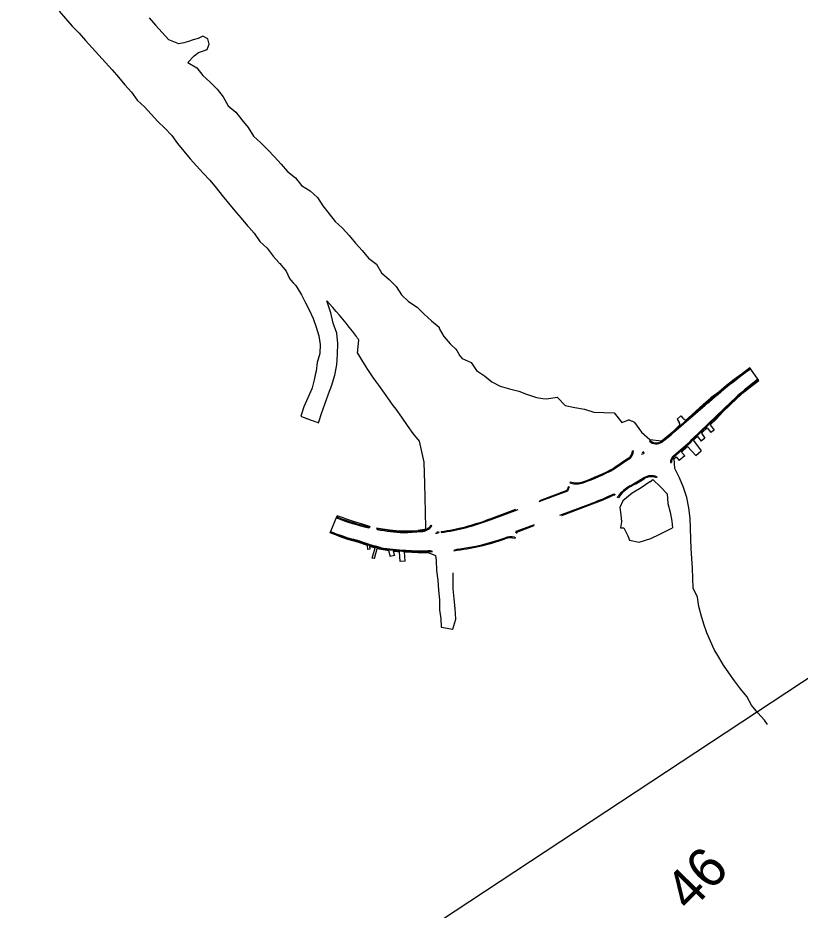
# Model space of a CAD drawing. Extents: x -5665 to 1997148, y 4 to 812485.
# Drawn here: x 1961620 to 1965586, y 802527 to 807051 of the extents above; entities that cross this region are included whole.
import ezdxf

# ---------------------------------------------------------------- set-up
doc = ezdxf.new("R2010")
doc.units = 0
for name, color, linetype in [('RD_PD_CstnLmt', 7, 'Continuous'), ('RD_PD_SW', 7, 'Continuous'), ('RD_SHT_ShtClip', 7, 'Continuous'), ('RD_SHT_TX', 7, 'Continuous')]:
    doc.layers.add(name, color=color, linetype=linetype)

msp = doc.modelspace()

# ---------------------------------------------------------------- linework, layer by layer
at = {"layer": 'RD_PD_CstnLmt'}
for p, q in [((1963199.4, 805601.5), (1963186.1, 805616.2)), ((1963342.6, 805350.3), (1963349.6, 805416.2)), ((1965095.2, 805090.2), (1965133, 805123.9)), ((1965058.2, 805056.4), (1965095.2, 805090.2)), ((1964981.6, 805033.9), (1964962.9, 805017)), ((1964962.9, 805017), (1964973.4, 804999.3)), ((1964981.6, 805033.9), (1964991.7, 805021.6)), ((1965007.8, 805012.6), (1965021.1, 805023)), ((1965021.1, 805023), (1965058.2, 805056.4)), ((1964745.4, 805000.5), (1964746.8, 804999.9)), ((1964945.4, 804957.6), (1964976.9, 804987.8)), ((1965115.5, 804972.6), (1965134, 804947.9)), ((1965130.6, 804986.9), (1965150.6, 804960.3)), ((1964908.6, 804926), (1964945.4, 804957.6)), ((1965066.6, 804928.3), (1965083.9, 804905.2)), ((1965085.6, 804945.1), (1965102.8, 804919.3)), ((1965150.6, 804960.3), (1965134, 804947.9)), ((1964883.5, 804906), (1964908.6, 804926)), ((1965045.5, 804908.8), (1965051.3, 804914.8)), ((1965045.5, 804908.8), (1965084.7, 804855.6)), ((1965102.8, 804919.3), (1965083.9, 804905.2)), ((1964984.8, 804849.7), (1965015.7, 804877.6)), ((1964984.8, 804849.7), (1965001.2, 804830.1)), ((1965015.7, 804877.6), (1965057.6, 804831.2)), ((1965057.6, 804831.2), (1965084.7, 804855.6)), ((1964948.5, 804817), (1964957.6, 804825.2)), ((1964957.6, 804825.2), (1964973.1, 804806.7)), ((1965001.2, 804830.1), (1964973.1, 804806.7)), ((1963204.3, 804440.1), (1963238.4, 804526)), ((1963274.8, 804513.8), (1963238.4, 804526)), ((1963274.8, 804513.8), (1963320.2, 804499.7)), ((1963320.2, 804499.7), (1963365.9, 804486.4)), ((1963365.9, 804486.4), (1963406.6, 804472.3)), ((1963243.2, 804425.4), (1963204.3, 804440.1)), ((1963437.9, 804465.4), (1963458, 804461.4)), ((1963458, 804461.4), (1963505.2, 804454.5)), ((1963505.2, 804454.5), (1963552.8, 804449.8)), ((1963552.8, 804449.8), (1963600.5, 804449.4)), ((1963600.5, 804449.4), (1963648.1, 804452.4)), ((1963682.7, 804456.3), (1963648.1, 804452.4)), ((1963243.2, 804425.4), (1963292.1, 804408.5)), ((1963292.1, 804408.5), (1963341.8, 804394.5)), ((1963341.8, 804394.5), (1963390.9, 804376.8)), ((1963390.9, 804376.8), (1963391.9, 804376.5)), ((1963404.9, 804356.5), (1963392.9, 804355.7)), ((1963403.4, 804372.9), (1963430.9, 804364.5)), ((1963416.7, 804312.2), (1963430.9, 804364.5)), ((1963428.2, 804309.1), (1963442.5, 804361.1)), ((1963442.5, 804361.1), (1963492.3, 804351.8)), ((1963498.6, 804351), (1963507.7, 804319.3)), ((1963522.4, 804347.8), (1963544.2, 804344.8)), ((1963522.4, 804347.8), (1963528.9, 804325.4)), ((1963557.9, 804294.2), (1963555.1, 804344.5)), ((1963583.8, 804295.6), (1963581.2, 804343.8)), ((1963586.5, 804343.7), (1963648.8, 804340.2)), ((1963648.8, 804340.2), (1963701.2, 804340.2)), ((1963701.2, 804340.2), (1963736.9, 804325.2)), ((1963428.2, 804309.1), (1963416.7, 804312.2)), ((1963528.9, 804325.4), (1963507.7, 804319.3)), ((1963583.8, 804295.6), (1963557.9, 804294.2))]:
    msp.add_line(p, q, dxfattribs=at)
for points in [[(1961829.4, 807084.3), (1961862.1, 807046.5), (1961895.3, 807009.1), (1961930, 806973.1), (1961963.4, 806935.8), (1961997.5, 806899.3), (1962030.4, 806861.6), (1962064.4, 806825), (1962097.9, 806787.9), (1962130.1, 806749.5), (1962162.4, 806711.3), (1962195.9, 806674.2), (1962224.5, 806632.6), (1962261.7, 806598.9), (1962296.2, 806562.7), (1962330.1, 806525.9), (1962365.8, 806490.8), (1962400.7, 806454.9), (1962429.2, 806413.3), (1962460.8, 806374.5), (1962492.9, 806336.5), (1962526.3, 806299.9), (1962560.1, 806263.6), (1962593.7, 806227.1), (1962625.1, 806188.7), (1962655.9, 806149.8), (1962687.2, 806110.7), (1962719.9, 806072.9), (1962728.5, 806062.9), (1962752.3, 806034.7), (1962785, 805996.7), (1962791.4, 805989.3), (1962817.5, 805958.3), (1962846.5, 805916.8), (1962883.3, 805882.7), (1962883.8, 805882.4), (1962915, 805842.7), (1962942.8, 805810.7), (1962945.4, 805807.7), (1962948.1, 805804.8), (1962980.4, 805766.5), (1962997.6, 805730), (1963003.8, 805720.3), (1963015.1, 805708.1), (1963015.1, 805708.1), (1963027.7, 805694.7), (1963034.7, 805685.1), (1963057.5, 805645.9), (1963078.9, 805606.5), (1963099.1, 805566.7), (1963117.6, 805525.7), (1963133.2, 805483.2), (1963146.1, 805439.4), (1963153.1, 805394.2), (1963150.5, 805348.4), (1963137, 805304.2), (1963131.9, 805259.6), (1963128.1, 805240.2), (1963122.5, 805215.6), (1963112.8, 805175.1), (1963111.2, 805169.8), (1963090.1, 805124.3), (1963070.4, 805078.3), (1963058.1, 805041), (1963055.1, 805030.6), (1963066.1, 805026.5), (1963077.4, 805022.4), (1963083, 805020.3), (1963084.9, 805019.6), (1963107.4, 805011.3), (1963118.7, 805007.2), (1963120.6, 805006.5), (1963126.2, 805004.4), (1963137.4, 805000.3), (1963143.6, 804998), (1963147.2, 805008.1), (1963160.2, 805045.2), (1963177, 805092.3), (1963192.8, 805139.7), (1963195.1, 805144.8), (1963211.6, 805188.3), (1963220.4, 805216.8), (1963226.8, 805239.5), (1963237.9, 805292), (1963240, 805345.6), (1963241.8, 805399.2), (1963237.3, 805452.8)], [(1962285.6, 807050.4), (1962318.2, 807013.2), (1962352.5, 806976.8), (1962385.5, 806939.3)], [(1962582.4, 806943.5), (1962557.4, 806958.2), (1962534.1, 806946.4), (1962509.1, 806939.5), (1962484.8, 806930.6), (1962462.2, 806924.7), (1962435.4, 806919.3), (1962385.5, 806939.3)], [(1962514.6, 806857.2), (1962536, 806875), (1962556.6, 806881.7), (1962579.1, 806890.4), (1962590.4, 806916.7), (1962582.4, 806943.5)], [(1962481.8, 806824.1), (1962514.6, 806857.2)], [(1962481.8, 806824.1), (1962527.1, 806797.6), (1962557.4, 806757.6), (1962594.6, 806723.8), (1962630.1, 806688.5), (1962661.7, 806649.7), (1962686.4, 806604.6), (1962725.7, 806572.8), (1962756.4, 806533.1), (1962788.3, 806494.5), (1962814.8, 806451.1), (1962852.1, 806417.4), (1962887.5, 806382), (1962921.5, 806345.3), (1962954.8, 806308.2), (1962987.8, 806271), (1963027.2, 806239.7), (1963058.6, 806201), (1963102.6, 806174.2), (1963138.8, 806139.7), (1963167, 806097.4), (1963197.9, 806057.8), (1963228.3, 806017.6), (1963265.9, 805983.9), (1963300.6, 805947.5), (1963332, 805908.1), (1963365.8, 805870.9), (1963397.4, 805832.1), (1963438.2, 805801.6), (1963463.6, 805757.2), (1963502.6, 805725), (1963537.6, 805689.2), (1963565.5, 805647.1), (1963601.1, 805611.9), (1963644, 805583.3), (1963680.4, 805548.8), (1963716.6, 805514.1), (1963756.4, 805482.7), (1963756.1, 805475.1), (1963779.2, 805435.8), (1963781.5, 805433), (1963812.3, 805398.3), (1963813.5, 805396.8), (1963840.9, 805371.8), (1963840.9, 805371.8), (1963846.5, 805364.9), (1963861.2, 805337.6), (1963872.1, 805323), (1963918.3, 805304.3), (1963945.7, 805262.2), (1963985.2, 805235.1), (1964023.1, 805205), (1964065.9, 805182.9), (1964113, 805170.7), (1964159.4, 805158.9), (1964198.4, 805142.3), (1964198.5, 805142.3), (1964203.3, 805140.7), (1964233.9, 805130.9), (1964250, 805126.5), (1964281.4, 805121.6), (1964299.8, 805118.9), (1964354.2, 805128.3), (1964394.2, 805085.1), (1964443.5, 805075.6), (1964493.1, 805067.7), (1964540.7, 805052), (1964591.8, 805049.3), (1964643.3, 805048), (1964681.6, 804998.9), (1964717.2, 805012.3)], [(1963237.3, 805452.8), (1963218.6, 805503.6), (1963206.9, 805555.5), (1963186.1, 805616.2)], [(1963342.6, 805350.3), (1963367.2, 805308.6), (1963392.9, 805267.8), (1963419.6, 805227.6), (1963433.2, 805208.2), (1963448, 805188.3), (1963477, 805147.5), (1963506.5, 805106.9), (1963516.8, 805092.3), (1963535.9, 805066.2), (1963565.5, 805025.7), (1963594.1, 804984.5), (1963623.4, 804943.8)], [(1965130.6, 804986.9), (1965161.1, 805017), (1965194.9, 805053), (1965230.2, 805087.5), (1965266.1, 805121.3), (1965302.9, 805154.1), (1965340.9, 805185.5), (1965376.8, 805212.5), (1965330.5, 805275.6), (1965293.6, 805247.9), (1965252.6, 805218), (1965213.2, 805186.1), (1965174.1, 805153.9), (1965133, 805123.9)], [(1964746.8, 804999.9), (1964781.3, 804949.6), (1964823.6, 804913.3), (1964883.5, 804906)], [(1965085.6, 804945.1), (1965088.8, 804947.9), (1965115.5, 804972.6)], [(1963623.4, 804943.8), (1963654.4, 804904), (1963678.5, 804797.5), (1963681.5, 804688.2), (1963685.3, 804547.2), (1963687.6, 804461.5), (1963682.7, 804456.3)], [(1965051.3, 804914.8), (1965066.6, 804928.3)], [(1965224.5, 803730), (1965197.9, 803769), (1965174.7, 803809.3), (1965150, 803848.5), (1965131.6, 803891), (1965114.1, 803933.9), (1965097.9, 803977.3), (1965084.8, 804021.9), (1965073.5, 804067.1), (1965065.3, 804113.2), (1965043.4, 804160.3), (1965043.1, 804210.4), (1965040.7, 804260.4), (1965036.6, 804310.2), (1965034.2, 804360.1), (1965032.4, 804410.1), (1965031.1, 804461.4), (1965028, 804514), (1965021.9, 804566.7), (1965011.4, 804618.9), (1964995.7, 804670), (1964974.1, 804718.8), (1964950.2, 804766.5), (1964948.5, 804817)], [(1964823.8, 804698.7), (1964839.3, 804710), (1964878.9, 804673.9), (1964912.7, 804637.7), (1964915.3, 804589.1), (1964927.1, 804544.3), (1964935.8, 804498.9), (1964938.5, 804464.6)], [(1964823.8, 804698.7), (1964779.9, 804668.8), (1964734.1, 804641.8)], [(1964734.1, 804641.8), (1964687.6, 804602.8), (1964687.4, 804602.3), (1964671.4, 804568.6), (1964676.6, 804530.7), (1964681.1, 804496.6), (1964675.8, 804465.4), (1964675.8, 804465.4), (1964693, 804464.8), (1964713.2, 804424.9), (1964721.7, 804403.1)], [(1964721.7, 804403.1), (1964770.2, 804392.2), (1964829.7, 804411.5), (1964874.4, 804434), (1964894.5, 804443.8), (1964908.2, 804450), (1964919.6, 804455.4), (1964938.5, 804464.6)], [(1963391.9, 804376.5), (1963392.9, 804355.7)], [(1963403.4, 804372.9), (1963404.9, 804356.5)], [(1963492.3, 804351.8), (1963496, 804351.3), (1963498.6, 804351)], [(1963544.2, 804344.8), (1963548.7, 804344.7), (1963555.1, 804344.5)], [(1963581.2, 804343.8), (1963586.5, 804343.7)], [(1963736.9, 804325.2), (1963740.5, 804299.5), (1963742.5, 804249.6), (1963748.8, 804199.9), (1963752.4, 804150), (1963758.6, 804100.3), (1963758.6, 804050.2), (1963765.3, 804003.7), (1963766.2, 803962.4), (1963766.9, 803962.3), (1963768.3, 803962), (1963795.9, 803957), (1963823.4, 803951.9), (1963824.9, 803951.6), (1963824.9, 803951.6), (1963840.2, 804002.5), (1963836.6, 804055.8), (1963832.4, 804105.6), (1963827.7, 804155.4), (1963826.7, 804205.5), (1963826.4, 804237.5)], [(1965420.7, 803468.9), (1965404.9, 803490.3), (1965372.2, 803528.1), (1965339, 803565.6), (1965315.4, 803610.7), (1965284.5, 803650), (1965254.4, 803689.9), (1965224.5, 803730)]]:
    msp.add_lwpolyline(points, dxfattribs=at)
for centre, radius, start, end in [((1961373.6, 803949.9), 2462, 37.2891, 42.1319), ((1961309.9, 804040.1), 2460.5, 34.0056, 34.7351), ((1965011, 805037.4), 25, 219.3511, 262.6705), ((1964597.5, 804688.2), 345.5, 64.6623, 69.7279), ((1964952, 804986.5), 25, 3.0273, 30.8982)]:
    msp.add_arc(centre, radius, start, end, dxfattribs=at)
at = {"layer": 'RD_PD_SW'}
for p, q in [((1965331.3, 805274.5), (1965334.2, 805270.5)), ((1965375.6, 805214.1), (1965372.7, 805218.1)), ((1964944.7, 804954.5), (1965102.3, 805090.4)), ((1964946.7, 804949.6), (1965105.6, 805086.7)), ((1965039.5, 804914.4), (1965238.8, 805105.6)), ((1965043, 804910.8), (1965242.2, 805102)), ((1964822.5, 804905.1), (1964826.1, 804908.6)), ((1964736.5, 804855.8), (1964741.5, 804855.8)), ((1964788.2, 804841.8), (1964790.9, 804838)), ((1964792.4, 804844.7), (1964794.8, 804841.2)), ((1964715.7, 804818.3), (1964641.3, 804767.3)), ((1964718.6, 804814.2), (1964643.9, 804763)), ((1964928.4, 804796.3), (1964933.4, 804796.1)), ((1964860.2, 804723.6), (1964858.2, 804719)), ((1964266.3, 804604.5), (1964405.2, 804656.1)), ((1964405.2, 804656.1), (1964412.9, 804677)), ((1964409.1, 804652.2), (1964417.6, 804675.4)), ((1964420.8, 804698.6), (1964418.4, 804692)), ((1964423.8, 804692.3), (1964423.1, 804690.4)), ((1964263.1, 804598), (1964409.1, 804652.2)), ((1964642.1, 804631.8), (1964645.4, 804629.6)), ((1964642.5, 804637.5), (1964648.2, 804633.8)), ((1964664.7, 804617.1), (1964658.8, 804620.9)), ((1964663.3, 804624), (1964661.6, 804625.1)), ((1964368.3, 804530.4), (1964531.1, 804590.9)), ((1964377.9, 804528.6), (1964532.8, 804586.2)), ((1963236.5, 804521.3), (1963234.7, 804516.6)), ((1964023.4, 804514.2), (1964145.6, 804559.6)), ((1964025.1, 804509.5), (1964156, 804558.2)), ((1963715.2, 804478.1), (1963719.1, 804475.1)), ((1964146.1, 804447.8), (1964240.3, 804482.8)), ((1964150.2, 804444), (1964238.3, 804476.7)), ((1963206.6, 804446), (1963204.8, 804441.4)), ((1963575.3, 804445.7), (1963665.4, 804451.4)), ((1963575.4, 804440.6), (1963665.7, 804446.4)), ((1963753.5, 804447), (1963753.9, 804442)), ((1963765.6, 804446.8), (1963765.9, 804441.8)), ((1964146.1, 804447.8), (1964143.5, 804438.5)), ((1964150.2, 804444), (1964148.3, 804437.3)), ((1964137.5, 804417.3), (1964138.1, 804419.2)), ((1964141, 804411.2), (1964142.9, 804418))]:
    msp.add_line(p, q, dxfattribs=at)
for centre, radius, start, end in [((1967047.5, 802933.9), 2902.4, 126.2503, 130.4535), ((1967047.5, 802933.9), 2897.4, 126.2503, 130.4551), ((1966156.8, 804148.8), 1326, 126.2503, 133.812), ((1966156.8, 804148.8), 1321, 126.2503, 133.812), ((1966999.3, 802891.6), 2904, 129.188, 130.7851), ((1966999.3, 802891.6), 2899, 129.1864, 130.7851), ((1964037.9, 806004.3), 1387.3, 307.543, 310.8192), ((1964037.9, 806004.3), 1392.3, 307.543, 310.751), ((1964857, 804938.5), 48, 223.9559, 307.543), ((1964857, 804938.5), 43, 223.9559, 307.543), ((1964013.2, 805984.2), 1482.4, 308.9999, 313.812), ((1964013.2, 805984.2), 1487.4, 308.9999, 313.812), ((1964688.6, 804857.9), 48, 304.4417, 357.4456), ((1964688.6, 804857.9), 53, 304.4417, 357.7496), ((1964013.2, 805984.2), 1380.4, 303.851, 304.1545), ((1964013.2, 805984.2), 1375.4, 304.1271, 304.5601), ((1964013.2, 805984.2), 1380.4, 304.362, 304.5961), ((1964976.4, 804794.8), 48, 128.9999, 178.2847), ((1964976.4, 804794.8), 43, 128.9999, 178.2847), ((1964013.2, 805984.2), 1369.4, 290.1469, 297.2985), ((1964013.2, 805984.2), 1374.4, 290.1469, 297.3115), ((1964013.2, 805984.2), 1486.4, 298.5815, 301.6403), ((1964013.2, 805984.2), 1491.4, 298.5815, 301.6403), ((1964831.3, 804656.6), 73, 66.7023, 121.6403), ((1964831.3, 804656.6), 68, 66.7023, 121.6403), ((1964452.9, 804785.9), 93, 249.8307, 290.1469), ((1964452.9, 804785.9), 98, 252.7523, 290.1469), ((1964809.7, 804522.7), 178, 118.5884, 145.3211), ((1964809.7, 804522.7), 173, 118.5884, 146.9307), ((1964013.2, 805984.2), 1486.4, 290.3874, 295.0451), ((1964013.2, 805984.2), 1491.4, 290.3874, 294.9383), ((1963642, 805540.6), 1096.9, 248.3103, 257.5395), ((1963642, 805540.6), 1101.9, 248.3103, 257.2657), ((1963661.1, 804519.3), 68, 273.6667, 322.7034), ((1963661.1, 804519.3), 73, 273.6667, 322.7034), ((1963616.7, 805536.3), 1099.6, 277.7805, 290.8813), ((1963616.7, 805536.3), 1104.6, 277.7639, 290.873), ((1963642, 805540.6), 1094.9, 289.5662, 290.3874), ((1963642, 805540.6), 1099.9, 289.5662, 290.3874), ((1963642, 805540.6), 1182.9, 248.3103, 255.03), ((1963642, 805540.6), 1177.9, 248.3103, 255.0414), ((1963394.7, 804480.1), 15, 286.9953, 314.9755), ((1963452, 804468.4), 15, 202.1143, 230.2794), ((1963642, 805540.6), 1096.9, 259.2915, 266.519), ((1963642, 805540.6), 1101.9, 259.5687, 266.5353), ((1963616.7, 805536.3), 1104.6, 276.2624, 277.0365), ((1963616.7, 805536.3), 1099.6, 276.6562, 277.0498), ((1963676, 805613), 1273, 276.9904, 289.0548), ((1963676, 805613), 1268, 277.9346, 289.0548), ((1964118.7, 804331.3), 88, 77.6265, 109.0548), ((1964118.7, 804331.3), 83, 74.3693, 109.0548), ((1963642, 805540.6), 1194.9, 261.1294, 267.3534), ((1963642, 805540.6), 1189.9, 261.1409, 267.3534), ((1963674.5, 805543.9), 1200.2, 265.8079, 272.2609), ((1963674.5, 805543.9), 1195.2, 265.8014, 271.2604), ((1963701.9, 804301), 48, 65.3719, 91.2604), ((1963857.6, 804309.6), 48, 97.9346, 123.8508)]:
    msp.add_arc(centre, radius, start, end, dxfattribs=at)
for points in [[(1963457.7, 804359.9), (1963455.9, 804360.4), (1963454.4, 804360.8), (1963452.4, 804361.3), (1963451.8, 804361.4), (1963450.5, 804361.8), (1963448.6, 804362.3), (1963446.7, 804362.8), (1963444.1, 804363.4), (1963442.9, 804363.8), (1963439.1, 804364.8), (1963436.5, 804365.5), (1963431.4, 804366.9), (1963428.9, 804367.6), (1963416.2, 804371.2), (1963406.1, 804374.2), (1963386, 804380.5), (1963376, 804383.8), (1963363.5, 804388.1), (1963361, 804388.9), (1963356, 804390.7), (1963353.5, 804391.5), (1963349.8, 804392.9), (1963348.6, 804393.3), (1963346.1, 804394.2), (1963344.9, 804394.7), (1963342.4, 804395.6), (1963341.1, 804396), (1963338.7, 804396.9), (1963337.5, 804397.3), (1963336.4, 804397.8)], [(1963458.7, 804364.8), (1963457.3, 804365.2), (1963455.9, 804365.5), (1963454, 804366), (1963453.4, 804366.2), (1963452.1, 804366.5), (1963451.4, 804366.7), (1963449.5, 804367.2), (1963448.2, 804367.5), (1963445.7, 804368.2), (1963444.4, 804368.5), (1963440.6, 804369.6), (1963438.1, 804370.3), (1963433, 804371.7), (1963430.4, 804372.4), (1963417.8, 804376), (1963407.6, 804379), (1963387.5, 804385.3), (1963377.5, 804388.6), (1963365, 804392.8), (1963362.5, 804393.7), (1963357.5, 804395.4), (1963355.1, 804396.3), (1963351.3, 804397.6), (1963350.1, 804398.1), (1963347.6, 804399), (1963346.4, 804399.4), (1963343.9, 804400.3), (1963342.7, 804400.8), (1963340.2, 804401.7), (1963339.1, 804402.1), (1963337.9, 804402.5)]]:
    msp.add_open_spline(points, degree=3, dxfattribs=at)
at = {"layer": 'RD_SHT_ShtClip'}
msp.add_lwpolyline([(1962404, 800141.4), (1962156.8, 800249.1), (1961619.9, 801061.9), (1967047, 804639.1), (1967746.1, 803578.5), (1967695.1, 802969), (1968000.2, 801689.9), (1968522.9, 801587.9), (1968575.1, 801281.2), (1968568.4, 800839.6), (1968542.7, 800594.7), (1964601.3, 797996.7), (1963740.9, 798826.2)], close=True, dxfattribs=at)

# ---------------------------------------------------------------- texts
at = {"layer": 'RD_SHT_TX'}
msp.add_text('46', height=200, rotation=45.6376, dxfattribs=at).set_placement((1965026, 802512.9))

doc.saveas('drawing.dxf')
